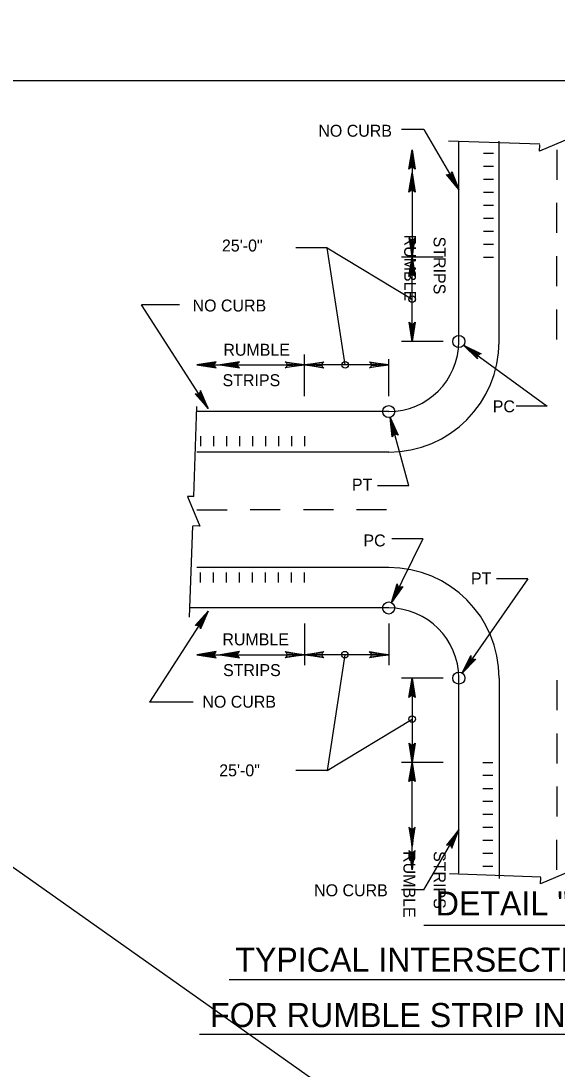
# Model space of a CAD drawing. Extents: x 632008 to 634206, y 294231 to 297795.
# Drawn here: x 633603.9 to 633738.6, y 295155.4 to 295418.6 of the extents above; entities that cross this region are included whole.
import ezdxf

# ---------------------------------------------------------------- set-up
doc = ezdxf.new("R2010")
doc.units = 0
for name, color, linetype in [('1', 7, 'Continuous'), ('2', 7, 'Continuous'), ('3', 7, 'Continuous'), ('Level 2', 7, 'Continuous')]:
    doc.layers.add(name, color=color, linetype=linetype)

msp = doc.modelspace()

# ---------------------------------------------------------------- linework, layer by layer
at = {"layer": '1'}
for p, q in [((633713.92, 295338.13), (633713.92, 295388.46)), ((633724.08, 295338.13), (633724.08, 295388.46)), ((633720.1, 295385.38), (633722.61, 295385.38)), ((633720.1, 295382.12), (633722.61, 295382.12)), ((633720.1, 295378.86), (633722.61, 295378.86)), ((633720.1, 295375.6), (633722.61, 295375.6)), ((633720.1, 295372.34), (633722.61, 295372.34)), ((633720.1, 295369.08), (633722.61, 295369.08)), ((633720.1, 295365.82), (633722.61, 295365.82)), ((633720.1, 295362.56), (633722.61, 295362.56)), ((633685.37, 295332.25), (633680.82, 295361.69)), ((633680.82, 295361.69), (633702.19, 295348.74)), ((633720.1, 295359.29), (633722.61, 295359.29)), ((633696.31, 295320.52), (633648.16, 295320.52)), ((633649.05, 295314.39), (633649.05, 295311.88)), ((633652.31, 295314.39), (633652.31, 295311.88)), ((633655.58, 295314.39), (633655.58, 295311.88)), ((633658.84, 295314.39), (633658.84, 295311.88)), ((633662.1, 295314.39), (633662.1, 295311.88)), ((633665.36, 295314.39), (633665.36, 295311.88)), ((633668.62, 295314.39), (633668.62, 295311.88)), ((633671.88, 295314.39), (633671.88, 295311.88)), ((633675.14, 295314.39), (633675.14, 295311.88)), ((633696.31, 295310.36), (633648.16, 295310.36)), ((633696.31, 295281.37), (633648.16, 295281.37)), ((633649.05, 295277.62), (633649.05, 295280.14)), ((633652.31, 295277.62), (633652.31, 295280.14)), ((633655.58, 295277.62), (633655.58, 295280.14)), ((633658.84, 295277.62), (633658.84, 295280.14)), ((633662.1, 295277.62), (633662.1, 295280.14)), ((633665.36, 295277.62), (633665.36, 295280.14)), ((633668.62, 295277.62), (633668.62, 295280.14)), ((633671.88, 295277.62), (633671.88, 295280.14)), ((633675.14, 295277.62), (633675.14, 295280.14)), ((633696.31, 295271.21), (633646.37, 295271.21)), ((633685.32, 295259.48), (633680.82, 295230.38)), ((633713.92, 295204.63), (633713.92, 295253.6)), ((633724.08, 295253.6), (633724.08, 295203.27)), ((633680.82, 295230.38), (633702.19, 295243.32)), ((633719.92, 295232.44), (633722.44, 295232.44)), ((633719.92, 295229.18), (633722.44, 295229.18)), ((633719.92, 295225.91), (633722.44, 295225.91)), ((633719.92, 295222.65), (633722.44, 295222.65)), ((633719.92, 295219.39), (633722.44, 295219.39)), ((633719.92, 295216.13), (633722.44, 295216.13)), ((633719.92, 295212.87), (633722.44, 295212.87)), ((633719.92, 295209.61), (633722.44, 295209.61)), ((633719.92, 295206.35), (633722.44, 295206.35)), ((633705.11, 295191.51), (633768.25, 295191.51))]:
    msp.add_line(p, q, dxfattribs=at)
msp.add_lwpolyline([(634127.07, 294839.62), (634127.07, 295403.62), (633341.07, 295403.62), (633341.07, 294839.62), (634127.07, 294839.62), (634127.07, 294865.98), (633927.07, 294865.98), (633927.07, 294930.66), (634127.07, 294930.66), (634127.07, 294959.62), (633927.07, 294959.62), (633927.07, 294839.62), (634005.87, 294839.62), (634005.87, 294865.98), (634005.87, 294839.62), (634082.87, 294839.62), (634082.87, 294865.98), (634082.87, 294853.66), (634127.07, 294853.66)], dxfattribs=at)
msp.add_lwpolyline([(634127.07, 294839.62), (634127.07, 295403.62), (633341.07, 295403.62), (633341.07, 294839.62), (634127.07, 294839.62), (634127.07, 294865.98), (633927.07, 294865.98), (633927.07, 294930.66), (634127.07, 294930.66), (634127.07, 294959.62), (633927.07, 294959.62), (633927.07, 294839.62), (634005.87, 294839.62), (634005.87, 294865.98), (634005.87, 294839.62), (634082.87, 294839.62), (634082.87, 294865.98), (634082.87, 294853.66), (634127.07, 294853.66)], dxfattribs=at)
msp.add_lwpolyline([(634127.07, 294839.62), (634127.07, 295403.62), (633341.07, 295403.62), (633341.07, 294839.62), (634127.07, 294839.62), (634127.07, 294865.98), (633927.07, 294865.98), (633927.07, 294930.66), (634127.07, 294930.66), (634127.07, 294959.62), (633927.07, 294959.62), (633927.07, 294839.62), (634005.87, 294839.62), (634005.87, 294865.98), (634005.87, 294839.62), (634082.87, 294839.62), (634082.87, 294865.98), (634082.87, 294853.66), (634127.07, 294853.66)], dxfattribs=at)
msp.add_lwpolyline([(634127.07, 294839.62), (634127.07, 295403.62), (633341.07, 295403.62), (633341.07, 294839.62), (634127.07, 294839.62), (634127.07, 294865.98), (633927.07, 294865.98), (633927.07, 294930.66), (634127.07, 294930.66), (634127.07, 294959.62), (633927.07, 294959.62), (633927.07, 294839.62), (634005.87, 294839.62), (634005.87, 294865.98), (634005.87, 294839.62), (634082.87, 294839.62), (634082.87, 294865.98), (634082.87, 294853.66), (634127.07, 294853.66)], dxfattribs=at)
msp.add_lwpolyline([(634127.07, 294839.62), (634127.07, 295403.62), (633341.07, 295403.62), (633341.07, 294839.62), (634127.07, 294839.62), (634127.07, 294865.98), (633927.07, 294865.98), (633927.07, 294930.66), (634127.07, 294930.66), (634127.07, 294959.62), (633927.07, 294959.62), (633927.07, 294839.62), (634005.87, 294839.62), (634005.87, 294865.98), (634005.87, 294839.62), (634082.87, 294839.62), (634082.87, 294865.98), (634082.87, 294853.66), (634127.07, 294853.66)], dxfattribs=at)
for centre in [(633702.19, 295348.74), (633685.37, 295332.25), (633685.32, 295259.48), (633702.19, 295243.32)]:
    msp.add_circle(centre, 0.821, dxfattribs=at)
for centre, radius, start, end in [((633696.31, 295338.13), 17.61, 270, 360), ((633696.31, 295338.13), 27.77, 270, 360), ((633696.31, 295253.6), 27.77, 0, 90), ((633696.31, 295253.6), 17.61, 0, 90)]:
    msp.add_arc(centre, radius, start, end, dxfattribs=at)
at = {"layer": '2'}
for p, q in [((633711.32, 295388.55), (633734.27, 295387.75)), ((633741.71, 295389.09), (633734.21, 295385.95)), ((633734.21, 295385.95), (633734.27, 295387.55)), ((633647.34, 295299.19), (633648.13, 295321.79)), ((633645.74, 295299.24), (633648.88, 295291.74)), ((633647.34, 295299.19), (633645.74, 295299.24)), ((633646.28, 295268.86), (633647.09, 295291.81)), ((633648.88, 295291.74), (633647.28, 295291.8)), ((633711.59, 295204.53), (633734.54, 295203.72)), ((633741.97, 295205.07), (633734.47, 295201.93)), ((633734.47, 295201.93), (633734.53, 295203.53)), ((633656.2, 295177.87), (633819.72, 295177.87)), ((633648.82, 295164.16), (633826.43, 295164.16))]:
    msp.add_line(p, q, dxfattribs=at)
at = {"layer": '3'}
for p, q in [((633705.11, 295391.33), (633699.49, 295391.33)), ((633705.11, 295391.33), (633713.92, 295376.28)), ((633702.19, 295386.28), (633702.19, 295359.29)), ((633738.58, 295386.28), (633738.58, 295378.74)), ((633738.58, 295365.38), (633738.58, 295372.92)), ((633680.82, 295361.69), (633673.01, 295361.69)), ((633738.58, 295352.02), (633738.58, 295359.56)), ((633710.03, 295359.29), (633699.49, 295359.29)), ((633702.19, 295338.13), (633702.19, 295359.29)), ((633643.79, 295347.34), (633634.18, 295347.34)), ((633651, 295321.3), (633634.18, 295347.34)), ((633738.58, 295338.66), (633738.58, 295346.2)), ((633710.03, 295338.13), (633699.49, 295338.13)), ((633715.14, 295337.24), (633736.15, 295321.88)), ((633675.14, 295324.41), (633675.14, 295334.9)), ((633696.31, 295324.41), (633696.31, 295333.69)), ((633648.16, 295332.25), (633675.14, 295332.25)), ((633696.31, 295332.25), (633675.14, 295332.25)), ((633736.15, 295321.88), (633728.34, 295321.88)), ((633701.34, 295301.84), (633696.7, 295319.06)), ((633701.34, 295301.84), (633693.54, 295301.84)), ((633648.16, 295295.87), (633655.7, 295295.87)), ((633669.06, 295295.87), (633661.52, 295295.87)), ((633682.42, 295295.87), (633674.88, 295295.87)), ((633695.78, 295295.87), (633688.24, 295295.87)), ((633704.91, 295288.61), (633696.98, 295272.57)), ((633704.91, 295288.61), (633697.1, 295288.61)), ((633731.23, 295278.55), (633714.79, 295254.85)), ((633731.23, 295278.55), (633723.43, 295278.55)), ((633651, 295270.43), (633636.24, 295247.57)), ((633675.14, 295267.32), (633675.14, 295256.83)), ((633696.31, 295267.32), (633696.31, 295256.83)), ((633648.16, 295259.48), (633675.14, 295259.48)), ((633696.31, 295259.48), (633675.14, 295259.48)), ((633710.03, 295253.6), (633699.49, 295253.6)), ((633702.19, 295253.6), (633702.19, 295232.44)), ((633738.58, 295253.07), (633738.58, 295245.53)), ((633647.23, 295247.57), (633636.24, 295247.57)), ((633738.58, 295239.71), (633738.58, 295232.17)), ((633710.03, 295232.44), (633699.49, 295232.44)), ((633702.19, 295205.45), (633702.19, 295232.44)), ((633680.82, 295230.38), (633673.01, 295230.38)), ((633738.58, 295226.35), (633738.58, 295218.81)), ((633705.11, 295200.4), (633713.92, 295215.45)), ((633738.58, 295205.45), (633738.58, 295212.99)), ((633705.11, 295200.4), (633699.49, 295200.4))]:
    msp.add_line(p, q, dxfattribs=at)
for points in [[(633701.61, 295381.67), (633701.95, 295381.85), (633702.19, 295386.28), (633701.61, 295381.67), (633701.41, 295381.44), (633702.19, 295386.28), (633702.41, 295381.85), (633702.74, 295381.69), (633702.19, 295386.28), (633702.96, 295381.44), (633702.74, 295381.69)], [(633701.61, 295375.85), (633701.95, 295376.02), (633702.19, 295380.46), (633701.61, 295375.85), (633701.41, 295375.61), (633702.19, 295380.46), (633702.41, 295376.03), (633702.74, 295375.86), (633702.19, 295380.46), (633702.96, 295375.61), (633702.74, 295375.86)], [(633712.09, 295380.55), (633711.89, 295380.23), (633713.92, 295376.28), (633712.09, 295380.55), (633712.15, 295380.85), (633713.92, 295376.28), (633711.49, 295379.99), (633711.13, 295379.97), (633713.92, 295376.28), (633710.81, 295380.07), (633711.13, 295379.97)], [(633701.61, 295363.9), (633701.95, 295363.73), (633702.19, 295359.29), (633701.61, 295363.9), (633701.41, 295364.14), (633702.19, 295359.29), (633702.41, 295363.73), (633702.74, 295363.89), (633702.19, 295359.29), (633702.96, 295364.14), (633702.74, 295363.89)], [(633701.61, 295354.69), (633701.95, 295354.86), (633702.19, 295359.29), (633701.61, 295354.69), (633701.41, 295354.45), (633702.19, 295359.29), (633702.41, 295354.86), (633702.74, 295354.7), (633702.19, 295359.29), (633702.96, 295354.45), (633702.74, 295354.7)], [(633702.77, 295342.74), (633702.44, 295342.57), (633702.19, 295338.13), (633702.77, 295342.74), (633702.97, 295342.98), (633702.19, 295338.13), (633701.97, 295342.56), (633701.64, 295342.72), (633702.19, 295338.13), (633701.42, 295342.98), (633701.64, 295342.72)], [(633718.52, 295334.05), (633718.58, 295334.42), (633715.14, 295337.24), (633718.52, 295334.05), (633718.6, 295333.75), (633715.14, 295337.24), (633718.85, 295334.8), (633719.18, 295334.97), (633715.14, 295337.24), (633719.51, 295335), (633719.18, 295334.97)], [(633652.77, 295332.83), (633652.6, 295332.49), (633648.16, 295332.25), (633652.77, 295332.83), (633653, 295333.03), (633648.16, 295332.25), (633652.59, 295332.03), (633652.75, 295331.7), (633648.16, 295332.25), (633653, 295331.48), (633652.75, 295331.7)], [(633658.59, 295332.83), (633658.42, 295332.49), (633653.98, 295332.25), (633658.59, 295332.83), (633658.83, 295333.03), (633653.98, 295332.25), (633658.41, 295332.03), (633658.57, 295331.7), (633653.98, 295332.25), (633658.83, 295331.48), (633658.57, 295331.7)], [(633670.54, 295332.83), (633670.71, 295332.49), (633675.14, 295332.25), (633670.54, 295332.83), (633670.3, 295333.03), (633675.14, 295332.25), (633670.71, 295332.03), (633670.55, 295331.7), (633675.14, 295332.25), (633670.3, 295331.48), (633670.55, 295331.7)], [(633679.75, 295331.67), (633679.58, 295332), (633675.14, 295332.25), (633679.75, 295331.67), (633679.99, 295331.47), (633675.14, 295332.25), (633679.58, 295332.47), (633679.74, 295332.8), (633675.14, 295332.25), (633679.99, 295333.02), (633679.74, 295332.8)], [(633691.7, 295332.83), (633691.87, 295332.49), (633696.31, 295332.25), (633691.7, 295332.83), (633691.47, 295333.03), (633696.31, 295332.25), (633691.88, 295332.03), (633691.71, 295331.7), (633696.31, 295332.25), (633691.47, 295331.48), (633691.71, 295331.7)], [(633648.02, 295324.86), (633648.39, 295324.9), (633651, 295321.3), (633648.02, 295324.86), (633647.72, 295324.95), (633651, 295321.3), (633648.78, 295325.14), (633648.97, 295325.46), (633651, 295321.3), (633649.02, 295325.79), (633648.97, 295325.46)], [(633697.35, 295314.46), (633697.62, 295314.71), (633696.7, 295319.06), (633697.35, 295314.46), (633697.21, 295314.18), (633696.7, 295319.06), (633698.07, 295314.83), (633698.43, 295314.76), (633696.7, 295319.06), (633698.71, 295314.58), (633698.43, 295314.76)], [(633699.54, 295276.44), (633699.17, 295276.44), (633696.98, 295272.57), (633699.54, 295276.44), (633699.83, 295276.57), (633696.98, 295272.57), (633698.75, 295276.64), (633698.52, 295276.93), (633696.98, 295272.57), (633698.44, 295277.25), (633698.52, 295276.93)], [(633648.02, 295266.87), (633648.39, 295266.83), (633651, 295270.43), (633648.02, 295266.87), (633647.72, 295266.78), (633651, 295270.43), (633648.78, 295266.59), (633648.97, 295266.27), (633651, 295270.43), (633649.02, 295265.94), (633648.97, 295266.27)], [(633652.77, 295260.06), (633652.6, 295259.73), (633648.16, 295259.48), (633652.77, 295260.06), (633653, 295260.26), (633648.16, 295259.48), (633652.59, 295259.26), (633652.75, 295258.93), (633648.16, 295259.48), (633653, 295258.71), (633652.75, 295258.93)], [(633658.59, 295260.06), (633658.42, 295259.73), (633653.98, 295259.48), (633658.59, 295260.06), (633658.83, 295260.26), (633653.98, 295259.48), (633658.41, 295259.26), (633658.57, 295258.93), (633653.98, 295259.48), (633658.83, 295258.71), (633658.57, 295258.93)], [(633670.54, 295260.06), (633670.71, 295259.73), (633675.14, 295259.48), (633670.54, 295260.06), (633670.3, 295260.26), (633675.14, 295259.48), (633670.71, 295259.26), (633670.55, 295258.93), (633675.14, 295259.48), (633670.3, 295258.71), (633670.55, 295258.93)], [(633679.75, 295258.9), (633679.58, 295259.24), (633675.14, 295259.48), (633679.75, 295258.9), (633679.99, 295258.7), (633675.14, 295259.48), (633679.58, 295259.7), (633679.74, 295260.03), (633675.14, 295259.48), (633679.99, 295260.25), (633679.74, 295260.03)], [(633691.7, 295260.06), (633691.87, 295259.73), (633696.31, 295259.48), (633691.7, 295260.06), (633691.47, 295260.26), (633696.31, 295259.48), (633691.88, 295259.26), (633691.71, 295258.93), (633696.31, 295259.48), (633691.47, 295258.71), (633691.71, 295258.93)], [(633717.89, 295258.3), (633717.52, 295258.35), (633714.79, 295254.85), (633717.89, 295258.3), (633718.19, 295258.38), (633714.79, 295254.85), (633717.13, 295258.61), (633716.95, 295258.93), (633714.79, 295254.85), (633716.91, 295259.26), (633716.95, 295258.93)], [(633701.61, 295248.99), (633701.95, 295249.16), (633702.19, 295253.6), (633701.61, 295248.99), (633701.41, 295248.76), (633702.19, 295253.6), (633702.41, 295249.17), (633702.74, 295249.01), (633702.19, 295253.6), (633702.96, 295248.76), (633702.74, 295249.01)], [(633702.77, 295237.04), (633702.44, 295236.87), (633702.19, 295232.44), (633702.77, 295237.04), (633702.97, 295237.28), (633702.19, 295232.44), (633701.97, 295236.87), (633701.64, 295237.03), (633702.19, 295232.44), (633701.42, 295237.28), (633701.64, 295237.03)], [(633701.61, 295227.83), (633701.95, 295228), (633702.19, 295232.44), (633701.61, 295227.83), (633701.41, 295227.59), (633702.19, 295232.44), (633702.41, 295228), (633702.74, 295227.84), (633702.19, 295232.44), (633702.96, 295227.59), (633702.74, 295227.84)], [(633701.61, 295215.88), (633701.95, 295215.71), (633702.19, 295211.27), (633701.61, 295215.88), (633701.41, 295216.12), (633702.19, 295211.27), (633702.41, 295215.7), (633702.74, 295215.87), (633702.19, 295211.27), (633702.96, 295216.12), (633702.74, 295215.87)], [(633712.09, 295211.18), (633711.89, 295211.5), (633713.92, 295215.45), (633712.09, 295211.18), (633712.15, 295210.88), (633713.92, 295215.45), (633711.49, 295211.74), (633711.13, 295211.76), (633713.92, 295215.45), (633710.81, 295211.66), (633711.13, 295211.76)], [(633701.61, 295210.06), (633701.95, 295209.88), (633702.19, 295205.45), (633701.61, 295210.06), (633701.41, 295210.29), (633702.19, 295205.45), (633702.41, 295209.88), (633702.74, 295210.05), (633702.19, 295205.45), (633702.96, 295210.29), (633702.74, 295210.05)]]:
    msp.add_lwpolyline(points, dxfattribs=at)
for centre in [(633713.92, 295338.13), (633696.31, 295320.52), (633696.31, 295271.21), (633713.92, 295253.6)]:
    msp.add_circle(centre, 1.52, dxfattribs=at)
at = {"layer": 'Level 2'}
msp.add_line((633301.07, 295418.62), (634142.07, 294824.62), dxfattribs=at)

# ---------------------------------------------------------------- texts
at = {"layer": '1'}
for s, height, p in [('DETAIL "G"', 6.039, (633708.13, 295193.98)), ('TYPICAL INTERSECTION DETAIL', 6.0395, (633657.79, 295179.85)), ('FOR RUMBLE STRIP INSTALLATION', 6.0395, (633651.44, 295165.96))]:
    msp.add_text(s, height=height, dxfattribs=at).set_placement(p)
at = {"layer": '3'}
for s, rotation, p in [('NO CURB', 360, (633678.64, 295389.55)), ('RUMBLE', 270, (633700.21, 295364.97)), ('25\'-0"', 360, (633654.43, 295360.73)), ('STRIPS', 270, (633707.59, 295364.47)), ('NO CURB', 360, (633649.51, 295246.16)), ('25\'-0"', 360, (633653.74, 295228.93)), ('RUMBLE', 270, (633700, 295210.15)), ('STRIPS', 270, (633707.62, 295210.15))]:
    msp.add_text(s, height=3, rotation=rotation, dxfattribs=at).set_placement(p)
for s, p in [('NO CURB', (633647.04, 295345.66)), ('RUMBLE', (633654.79, 295334.55)), ('STRIPS', (633654.58, 295326.91)), ('PC', (633722.45, 295320.34)), ('PT', (633687.08, 295300.69)), ('PC', (633689.97, 295286.66)), ('PT', (633716.99, 295277.13)), ('RUMBLE', (633654.54, 295261.82)), ('STRIPS', (633654.71, 295254.1)), ('NO CURB', (633677.58, 295198.81))]:
    msp.add_text(s, height=3, dxfattribs=at).set_placement(p)

doc.saveas('drawing.dxf')
